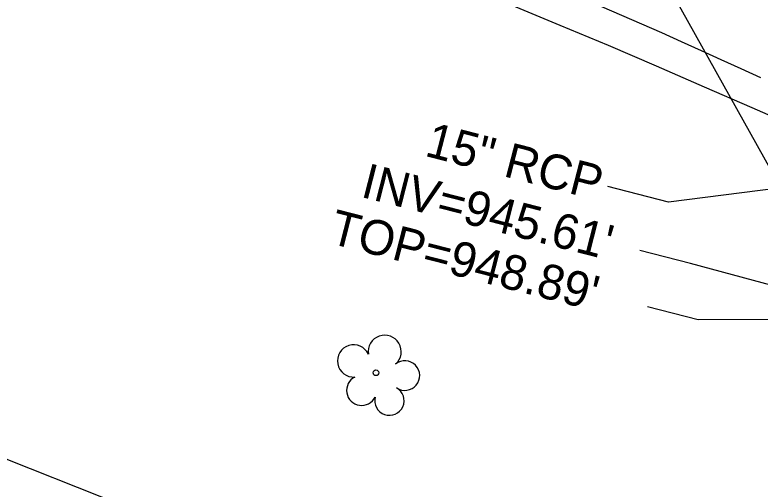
# Model space of a CAD drawing. Extents: x 1182322 to 1186765, y 572295 to 575411.
# Drawn here: x 1183659.7 to 1183745.3, y 574148.9 to 574203.3 of the extents above; entities that cross this region are included whole.
import ezdxf

# ---------------------------------------------------------------- set-up
doc = ezdxf.new("R2010")
doc.units = 0
for name, color, linetype in [('Exist Right of Way Line', 7, 'Continuous'), ('Exist Roads EOP', 7, 'Continuous'), ('Exist Roads EOT', 7, 'Continuous'), ('Exist Structure Minor Drop Inlet Leader', 7, 'Continuous'), ('Exist Structure Minor Drop Inlet Top Elevation', 7, 'Continuous'), ('Exist Structure Minor Pipes RCP 15 Inch', 7, 'Continuous'), ('Exist Structure Minor Pipes RCP 15 Inch Invert', 7, 'Continuous'), ('Exist Structure Minor Pipes RCP 15 Inch Leader', 7, 'Continuous'), ('Exist Structure Minor Pipes RCP 15 Inch Text', 7, 'Continuous'), ('Exist Utilities Telephone UG Conduit SUE LOS B', 7, 'Continuous'), ('Exist Vegetation Tree CELL', 7, 'Continuous')]:
    doc.layers.add(name, color=color, linetype=linetype)

msp = doc.modelspace()

# ---------------------------------------------------------------- linework, layer by layer
at = {"layer": 'Exist Right of Way Line'}
for centre, radius, start, end in [((1183748.442, 574204.91), 88, 248.49303, 248.49303), ((1182574.745, 571226.372), 3113.446, 68.493028, 71.121205)]:
    msp.add_arc(centre, radius, start, end, dxfattribs=at)
at = {"layer": 'Exist Roads EOP'}
msp.add_lwpolyline([(1183749.893, 574190.242), (1183744.394, 574192.64), (1183738.891, 574195.031), (1183733.389, 574197.423), (1183727.881, 574199.802), (1183722.342, 574202.109), (1183716.8, 574204.406), (1183711.257, 574206.703), (1183705.714, 574208.999), (1183700.166, 574211.283), (1183694.616, 574213.564), (1183693.301, 574214.105)], dxfattribs=at)
at = {"layer": 'Exist Roads EOT'}
msp.add_lwpolyline([(1183745.379, 574196.102), (1183743.103, 574197.135), (1183740.827, 574198.169), (1183738.551, 574199.203), (1183736.275, 574200.237), (1183733.995, 574201.264), (1183731.704, 574202.265), (1183729.409, 574203.255), (1183727.114, 574204.245), (1183724.818, 574205.235), (1183722.522, 574206.225), (1183720.227, 574207.215), (1183717.928, 574208.198), (1183715.618, 574209.153), (1183713.305, 574210.101), (1183710.992, 574211.049), (1183708.678, 574211.996), (1183706.365, 574212.946), (1183704.053, 574213.896), (1183701.741, 574214.846), (1183701.121, 574215.098)], dxfattribs=at)
at = {"layer": 'Exist Structure Minor Drop Inlet Leader'}
msp.add_lwpolyline([(1183755.029, 574168.357), (1183738.169, 574168.319), (1183732.357, 574169.807)], dxfattribs=at)
at = {"layer": 'Exist Structure Minor Pipes RCP 15 Inch'}
msp.add_line((1183688.315, 574289.877), (1183755.177, 574169.963), dxfattribs=at)
at = {"layer": 'Exist Structure Minor Pipes RCP 15 Inch Leader'}
for points in [[(1183747.412, 574183.406), (1183734.767, 574181.816), (1183727.808, 574183.598)], [(1183755.177, 574169.963), (1183737.307, 574174.786), (1183731.495, 574176.274)]]:
    msp.add_lwpolyline(points, dxfattribs=at)
at = {"layer": 'Exist Utilities Telephone UG Conduit SUE LOS B'}
msp.add_lwpolyline([(1183184.204, 574290.245), (1183230.461, 574277.801), (1183276.74, 574264.857), (1183322.883, 574252.134), (1183369.359, 574239.838), (1183416.406, 574227.818), (1183461.9, 574217.608), (1183507.97, 574205.101), (1183555.779, 574190.969), (1183600.287, 574174.703), (1183642.376, 574158.775), (1183685.834, 574141.537), (1183729.441, 574124.528), (1183772.612, 574105.481), (1183815.477, 574084.718), (1183856.895, 574064.888), (1183910.265, 574040.724), (1183938.646, 574025.644), (1184017.127, 573974.93), (1184056.255, 573949.513), (1184095.954, 573918.751), (1184120.249, 573896.118), (1184153.183, 573876.374), (1184177.599, 573863.32)], dxfattribs=at)
at = {"layer": 'Exist Vegetation Tree CELL'}
msp.add_line((1183701.159, 574162.226), (1183701.159, 574162.226), dxfattribs=at)
msp.add_circle((1183701.159, 574162.226), 0.326, dxfattribs=at)
for centre, radius, start, end in [((1183702.165, 574164.64), 1.899, 311.47347, 188.5723), ((1183698.599, 574163.586), 1.856, 24.53744, 274.08572), ((1183704.49, 574161.896), 1.698, 235.65453, 128.93236), ((1183699.516, 574160.198), 1.727, 117.03598, 333.71807), ((1183702.703, 574159.023), 1.689, 165.93945, 60.60341)]:
    msp.add_arc(centre, radius, start, end, dxfattribs=at)

# ---------------------------------------------------------------- texts
at = {"layer": 'Exist Structure Minor Drop Inlet Top Elevation'}
msp.add_text("TOP=948.89'", height=4, rotation=345.64052, dxfattribs=at).set_placement((1183695.627, 574177.145))
at = {"layer": 'Exist Structure Minor Pipes RCP 15 Inch Invert'}
msp.add_text("INV=945.61'", height=4, rotation=345.64052, dxfattribs=at).set_placement((1183699.282, 574182.456))
at = {"layer": 'Exist Structure Minor Pipes RCP 15 Inch Text'}
msp.add_text('15" RCP', height=4, rotation=345.47652, dxfattribs=at).set_placement((1183706.637, 574187.167))

doc.saveas('drawing.dxf')
